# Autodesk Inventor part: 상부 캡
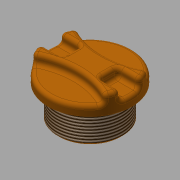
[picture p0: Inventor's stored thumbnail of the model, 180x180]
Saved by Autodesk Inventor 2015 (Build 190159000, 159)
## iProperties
Created: 2016-09
Part Number: 상부 캡
Material: ABS 플라스틱
Document SubType Name: Modeling
Designer: mduedu
Density: 1.493 g/cm^3
Mass: 32.6939 g
Surface Area: 67.9045 cm^2
Volume: 21.8981 cm^3
Appearance: 주황색
Author: mduedu
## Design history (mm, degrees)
sketch "스케치1"
  geometry: C1 r 22.5 at (0, 0); 1 further point
  constraints: 1 centre point, 1 coincident
  dimensions: "d0" = 45 diameter of C1
extrude "돌출1" new body sketch "스케치1" distance "d1" = 10; taper "d2" = 0 deg
sketch "스케치2" dims "d4" = 80
  geometry: C1 r 22.5 at (0, 0) reference; 3 further points
  constraints: 3 vertical alignment, 2 other
  dimensions: "d3" = 7 distance of point (0, 7) point (0, 0)
extrude "돌출2" cut sketch "스케치2" distance "d5" = 5; taper "d6" = 0 deg
sketch "스케치3"
  geometry: L1 (-22.5, 0)-(0, 0); L2 (-21.937, 5)-(-10, 5); L3 (-10, 5)-(-10, -5); L4 (-10, -5)-(-21.937, -5); A1 r 22.5 centre (0, 0) between (-19.118, 11.864) and (-19.118, -11.864) reference; A2 r 22.5 centre (0, 0) between (-21.937, 5) and (-21.937, -5); 1 further point
  constraints: 8 end point, 5 point on circle, 2 horizontal, 1 centre point, 1 coincident, 1 parallel, 1 perpendicular, 1 symmetric about line
  dimensions: "d7" = 10 distance from line of L3 point (0, 0); "d8" = 10 distance of L2.end L3.end
extrude "돌출3" cut sketch "스케치3" distance "d9" = 5; taper "d10" = 0 deg
fillet "모깎기1" dims "d11" = 2
fillet "모깎기2" dims "d12" = 2
fillet "모깎기3" dims "d13" = 2
sketch "스케치4"
  geometry: C1 r 17.5 at (0, 0); 1 further point
  constraints: 1 centre point, 1 coincident
  dimensions: "d14" = 35 diameter of C1
extrude "돌출4" join sketch "스케치4" distance "d15" = 17; taper "d16" = 0 deg
sketch "스케치5"
  geometry: C1 r 12.5 at (0, 0); 1 further point
  constraints: 1 centre point, 1 coincident
  dimensions: "d17" = 25 diameter of C1
extrude "돌출5" cut sketch "스케치5" distance "d18" = 10; taper "d19" = 0 deg
fillet "모깎기4" dims "d20" = 3
sketch "스케치6"
  geometry: L1 (0, 22.5)-(0, -22.5) reference; L2 (0, 17.5)-(-1, 17.5); L3 (-1, 17.5)-(-1, 16.5); L4 (-1, 16.5)-(0, 16.5); L5 (0, 16.5)-(0, 17.5); L6 (0, 17.5)-(-17, 17.5) reference; L7 (-22.401, 0)-(15.404, 0) reference; 1 further point
  constraints: 8 end point, 2 parallel, 1 collinear, 1 horizontal, 1 perpendicular, 1 point on line
  dimensions: "d26" = 1 distance of L2.start L2.end; "d28" = 1 distance of L2.end L3.end
revolve "회전1" sketch "스케치6" stored, may be unused: angle "d29" = 90 deg
feature "스레드1" dims "d21" = 10, "d22" = 0
chamfer "모따기1" distance "d23" = 1; stored, may be unused: second distance "d24" = 2, angle "d25" = 45 deg
chamfer "모따기2" distance "d30" = 1; stored, may be unused: second distance "d31" = 2, angle "d32" = 45 deg
node "솔리드1"
mirror "대칭1"
mirror "대칭2"
node "투영된 루프1"
